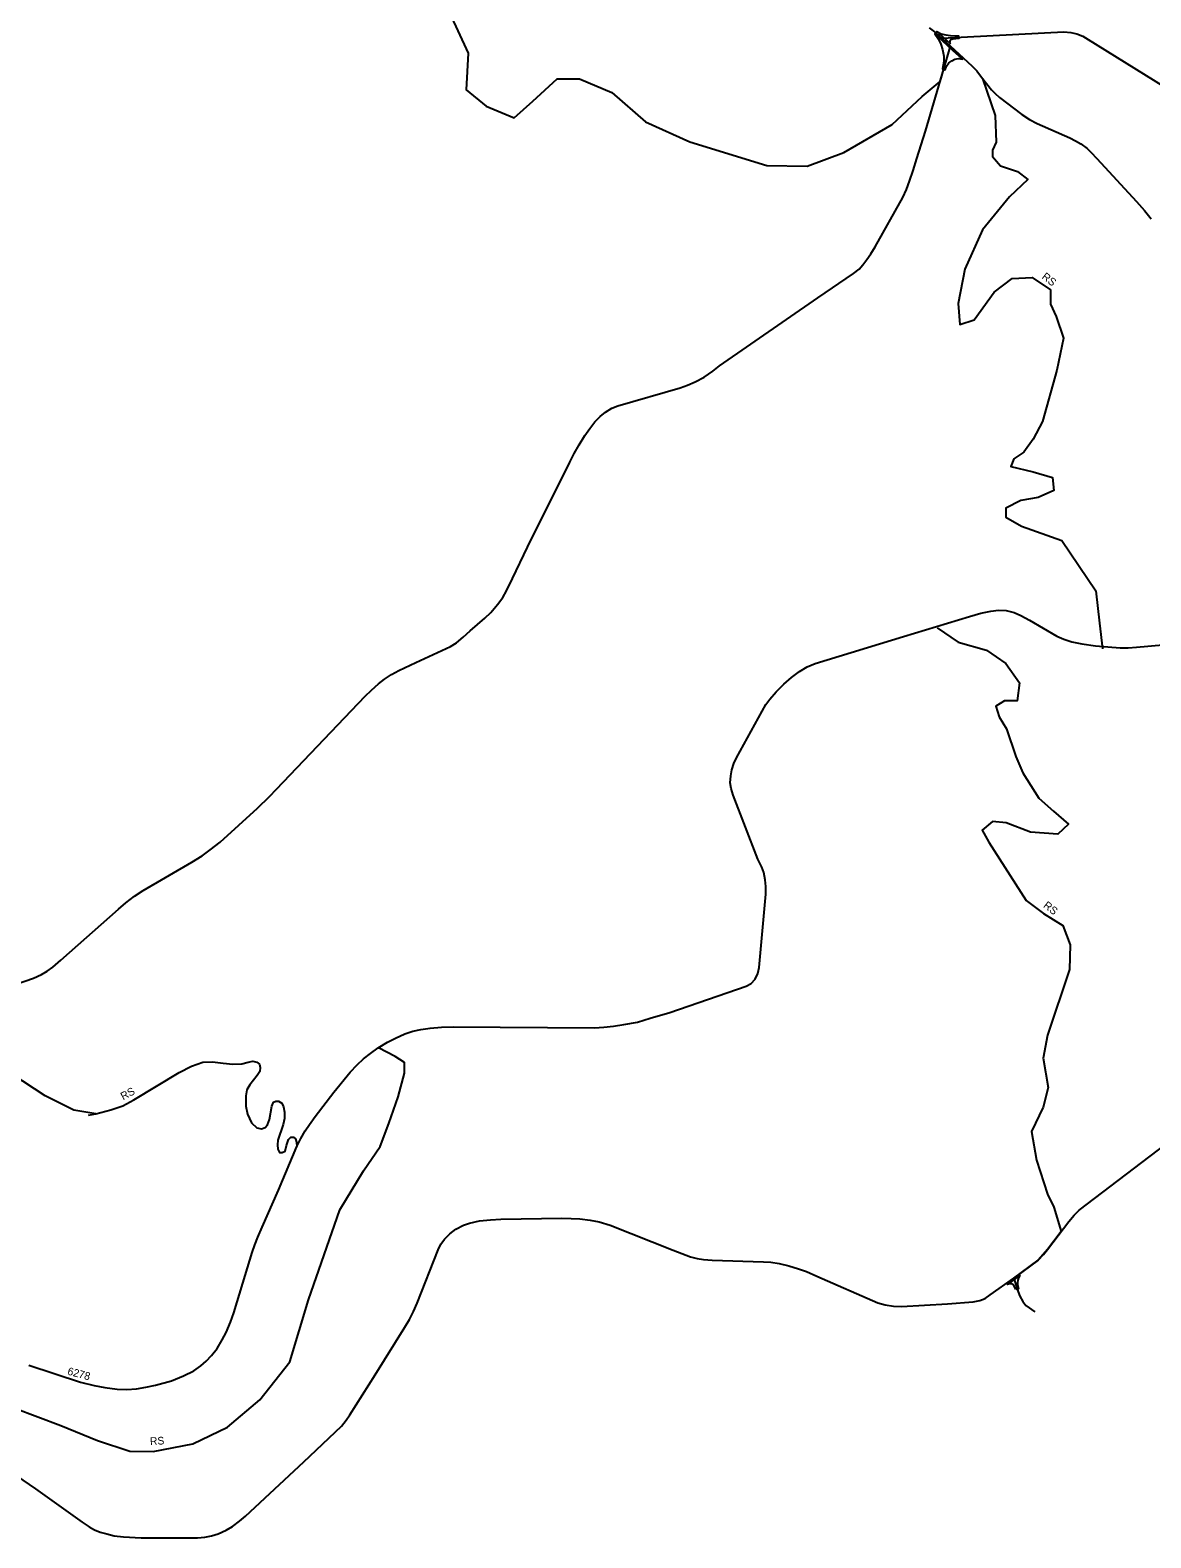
# Model space of a CAD drawing. Extents: x -546703 to -534152, y -1046534 to -1035676.
# Drawn here: x -544245 to -542791, y -1045260 to -1043304 of the extents above; entities that cross this region are included whole.
import ezdxf

# ---------------------------------------------------------------- set-up
doc = ezdxf.new("R2010")
doc.units = 0
doc.layers.add('Vrstva 11', color=7, linetype='Continuous')
doc.layers.add('Vrstva 22', color=7, linetype='Continuous')

msp = doc.modelspace()

# ---------------------------------------------------------------- linework, layer by layer
at = {"layer": 'Vrstva 11'}
for points in [[(-543078.1, -1043300.5), (-543069.5, -1043306.9), (-543062, -1043313.8), (-543050.4, -1043324.4), (-543022.8, -1043349.7), (-543016.5, -1043356.5), (-543010.3, -1043364.4), (-542997.5, -1043381.2), (-542992.8, -1043385.9), (-542987, -1043391.1), (-542958, -1043413.2), (-542948, -1043419.6), (-542937.9, -1043424.7), (-542895.5, -1043443.3), (-542888.3, -1043447.1), (-542881.4, -1043451.2), (-542873.1, -1043457.2), (-542868, -1043462.2), (-542860.8, -1043470), (-542809.2, -1043526.1), (-542798.9, -1043537.6), (-542790, -1043548.6)], [(-543062, -1043313.8), (-542903.6, -1043305.9), (-542894.5, -1043306.7), (-542886.4, -1043308.3), (-542878.9, -1043311.3), (-542872.1, -1043315.6), (-542762.3, -1043383.6)], [(-544317.4, -1044560.2), (-544240.7, -1044533.7), (-544230.6, -1044529.3), (-544223.3, -1044524.8), (-544216, -1044519.4), (-544205.6, -1044510.7), (-544130.5, -1044444.2), (-544121, -1044436), (-544109.9, -1044427.5), (-544098.6, -1044420.2), (-544035.2, -1044383.4), (-544022.1, -1044375.2), (-544011.4, -1044367.5), (-543998.7, -1044357.4), (-543950, -1044313.2), (-543934.7, -1044298), (-543925.6, -1044288.5), (-543810.3, -1044168), (-543802.1, -1044159.9), (-543793.2, -1044152), (-543785.1, -1044145.9), (-543776.2, -1044139.9), (-543766.7, -1044134.4), (-543744.7, -1044124.3), (-543699.5, -1044103.5), (-543691.9, -1044098.7), (-543683, -1044091.2), (-543674.1, -1044083.3), (-543654.9, -1044066.8), (-543647.3, -1044059.1), (-543638.4, -1044049), (-543631.9, -1044039.7), (-543627.1, -1044031), (-543619, -1044015.3), (-543599.6, -1043974.7), (-543544.7, -1043864), (-543538.9, -1043852.9), (-543532.4, -1043841.6), (-543525.1, -1043829.7), (-543518.7, -1043820.4), (-543512.2, -1043811.9), (-543505.4, -1043804.8), (-543498.5, -1043799.2), (-543490.2, -1043794.3), (-543482.4, -1043791.1), (-543401.6, -1043767.9), (-543391.9, -1043764.2), (-543382.2, -1043760), (-543370.3, -1043753.7), (-543359.2, -1043746.3), (-543350.5, -1043739.4), (-543222.6, -1043650.9), (-543176.4, -1043619.2), (-543169.3, -1043613.6), (-543164.2, -1043607.9), (-543159, -1043601.2), (-543153.8, -1043593.8), (-543148.5, -1043584.9), (-543112.6, -1043520.9), (-543107.7, -1043510.4), (-543103.7, -1043499.7), (-543099.1, -1043485.7), (-543094.2, -1043470.2), (-543083.1, -1043434.8), (-543050.4, -1043324.4)], [(-544246.9, -1045036.3), (-544179.8, -1045058.1), (-544162.3, -1045062.3), (-544148.1, -1045065.2), (-544132.1, -1045067.2), (-544119.9, -1045067.5), (-544107.3, -1045066.7), (-544095.1, -1045064.8), (-544082.6, -1045062), (-544061.6, -1045056.3), (-544046.1, -1045050.1), (-544032.9, -1045043.3), (-544023.5, -1045037.1), (-544016.7, -1045030.9), (-544009.7, -1045023.4), (-544002.7, -1045014.6), (-543995.8, -1045003.4), (-543991, -1044993.6), (-543985.3, -1044980.4), (-543981, -1044968), (-543969.2, -1044929.5), (-543957.2, -1044890.1), (-543953.7, -1044880.1), (-543949.6, -1044869.9), (-543944.3, -1044857.2), (-543922.8, -1044808.8), (-543898.9, -1044752.4), (-543893.8, -1044741.9), (-543888.1, -1044731.9), (-543882.8, -1044723.7), (-543875.4, -1044713.5), (-543850.9, -1044681.8), (-543829.9, -1044655.9), (-543820.9, -1044646.3), (-543812.4, -1044638.4), (-543803.5, -1044631.6), (-543793.5, -1044624.4), (-543781.2, -1044616.9), (-543770.9, -1044611.6), (-543758.7, -1044606.2), (-543748.7, -1044602.7), (-543738.2, -1044600.4), (-543725.8, -1044598.7), (-543711.1, -1044597.5), (-543696, -1044597), (-543512.5, -1044598.2), (-543500.8, -1044597.5), (-543488, -1044596), (-543474.8, -1044594.2), (-543457.1, -1044590.9), (-543440.3, -1044585.9), (-543414.8, -1044578.5), (-543315.9, -1044544.1), (-543309.5, -1044540.8), (-543304, -1044535.1), (-543300.7, -1044527.8), (-543298.8, -1044519.9), (-543298.2, -1044510.4), (-543290.5, -1044425), (-543290.2, -1044414.8), (-543291, -1044406.1), (-543293, -1044396.8), (-543295.7, -1044389.8), (-543300.7, -1044379.6), (-543332.9, -1044296.3), (-543335.5, -1044287.6), (-543336.4, -1044280.3), (-543335.9, -1044271.3), (-543334.5, -1044263.3), (-543331.9, -1044255.1), (-543328.4, -1044247.9), (-543290.3, -1044178.8), (-543285.3, -1044171.8), (-543277, -1044162.1), (-543267, -1044152.3), (-543257.1, -1044143.8), (-543246.5, -1044135.8), (-543236.5, -1044129.7), (-543226.1, -1044125.4), (-543111.4, -1044090.4), (-543026, -1044064.5), (-543011.1, -1044060.2), (-542998.3, -1044057.5), (-542988.1, -1044056.3), (-542978.4, -1044056.8), (-542968.1, -1044059.2), (-542959.1, -1044063.2), (-542947.9, -1044069.3), (-542912.6, -1044090.2), (-542903.4, -1044094), (-542893, -1044097.4), (-542880.2, -1044100), (-542862.2, -1044102.4), (-542830.2, -1044105), (-542819.8, -1044105), (-542809, -1044104.5), (-542726.1, -1044097)], [(-544330.5, -1045134), (-544238.5, -1045196.6), (-544177.9, -1045239.8), (-544168.8, -1045245.8), (-544161.7, -1045249.9), (-544154.3, -1045252.7), (-544145.9, -1045255.2), (-544136.3, -1045257.4), (-544124, -1045259), (-544101.1, -1045260.1), (-544027.9, -1045260.2), (-544018.4, -1045259.4), (-544009.7, -1045257.8), (-544001, -1045255.2), (-543990.9, -1045250.3), (-543982.4, -1045245.4), (-543973.6, -1045238.7), (-543965.6, -1045232.1), (-543890.2, -1045161.7), (-543841.3, -1045115.1), (-543835.1, -1045107.6), (-543830.2, -1045100.5), (-543797.5, -1045048.8), (-543758.7, -1044986.6), (-543753, -1044976.8), (-543747.6, -1044966.3), (-543742.8, -1044955.8), (-543715.8, -1044886.6), (-543712, -1044879), (-543707.3, -1044872.4), (-543700.7, -1044865.8), (-543692.6, -1044859.8), (-543682.6, -1044854.4), (-543674.8, -1044851.7), (-543661.9, -1044848.9), (-543647.8, -1044847.3), (-543634.4, -1044846.6), (-543555, -1044845.2), (-543542.9, -1044845.6), (-543531.7, -1044846.3), (-543518.3, -1044847.8), (-543506.7, -1044850.3), (-543492.4, -1044854.4), (-543410.4, -1044887), (-543388, -1044895.4), (-543379.5, -1044897.7), (-543371.3, -1044899.1), (-543360.1, -1044899.9), (-543293.5, -1044901.8), (-543283.7, -1044902.6), (-543273.1, -1044904), (-543260.5, -1044907.2), (-543247.8, -1044910.9), (-543237.3, -1044914.6), (-543224.2, -1044920.5), (-543145, -1044955.1), (-543135.4, -1044957.8), (-543124.7, -1044959.4), (-543114, -1044959.8), (-543054.7, -1044956.5), (-543021.2, -1044953.9), (-543012.4, -1044952.3), (-543005.7, -1044949.5), (-542999, -1044945), (-542968.4, -1044923.4), (-542937, -1044899.7), (-542929.8, -1044892.3), (-542924.6, -1044885.9), (-542897.1, -1044849.6), (-542890.2, -1044841.4), (-542883.5, -1044834.9), (-542771.4, -1044749.6)], [(-542968.4, -1044923.4), (-542964.2, -1044937.6), (-542960.7, -1044946.6), (-542956.9, -1044953.6), (-542952.8, -1044958.7), (-542941.3, -1044967.1)]]:
    msp.add_lwpolyline(points, dxfattribs=at)
for points in [[(-543051.7, -1043325.9), (-543063.3, -1043315.3), (-543070.8, -1043308.5), (-543066.2, -1043315.4), (-543063, -1043321.9), (-543061, -1043328.7), (-543059.3, -1043337.2), (-543059.1, -1043344.3), (-543060.9, -1043353.8), (-543057.6, -1043355), (-543055.7, -1043350.2), (-543052.6, -1043346.1), (-543049, -1043343.3), (-543045, -1043341.1), (-543040.2, -1043340.3), (-543035, -1043341.2)], [(-543060.6, -1043312.3), (-543068.2, -1043305.4), (-543062.7, -1043308.2), (-543056.7, -1043309.7), (-543050.4, -1043310.6), (-543040, -1043310.9), (-543039.6, -1043314.4), (-543047.7, -1043315.4), (-543050.2, -1043316.3), (-543051.6, -1043317.9), (-543051.7, -1043319.2), (-543051.1, -1043321)], [(-542965.9, -1044938.1), (-542968, -1044933.6), (-542969.7, -1044931.5), (-542971.5, -1044930.6), (-542973.4, -1044930.4), (-542976.8, -1044931.5), (-542967.4, -1044924.8), (-542960.5, -1044919.6), (-542962.3, -1044922.8), (-542963.1, -1044925.8), (-542963.5, -1044929.2), (-542963.5, -1044932.4), (-542962.5, -1044937)]]:
    msp.add_lwpolyline(points, close=True, dxfattribs=at)
at = {"layer": 'Vrstva 22'}
for points in [[(-543700.9, -1043281.1), (-543676.7, -1043333.5), (-543679.1, -1043381.1), (-543653.3, -1043402.1), (-543617, -1043417.4), (-543592.8, -1043395.6), (-543561.3, -1043366.6), (-543532.3, -1043366.6), (-543490.3, -1043384.3), (-543446.4, -1043422.7), (-543389.1, -1043448.5), (-543289.1, -1043479.1), (-543236.6, -1043479.9), (-543189.1, -1043462.2), (-543126.1, -1043425.9), (-543087.4, -1043389.6), (-543064, -1043370.3), (-543050.4, -1043324.4)], [(-543009, -1043366.1), (-542992.8, -1043414.3), (-542991.2, -1043449), (-542996, -1043459.4), (-542996, -1043467.5), (-542985.5, -1043479.6), (-542963.8, -1043486.9), (-542950, -1043497.3), (-542974.2, -1043519.9), (-543008.9, -1043562.7), (-543031.9, -1043613.9), (-543040.8, -1043658.3), (-543038.4, -1043685.7), (-543019.8, -1043679.3), (-542994, -1043643.8), (-542970.6, -1043626), (-542944.8, -1043624.4), (-542920.6, -1043640.6), (-542920.6, -1043659.1), (-542913.3, -1043675.2), (-542903.7, -1043703.5), (-542912.5, -1043744.6), (-542931.1, -1043811.6), (-542943.2, -1043834.2), (-542955.3, -1043851.1), (-542968.2, -1043860), (-542972.2, -1043869.7), (-542943.2, -1043876.9), (-542918.2, -1043884.2), (-542916.6, -1043901.1), (-542936.7, -1043910), (-542959.3, -1043914), (-542978.7, -1043923.7), (-542978.7, -1043935.8), (-542958.5, -1043947.1), (-542906.1, -1043965.7), (-542862.1, -1044031.4), (-542857.3, -1044073.3), (-542853.2, -1044106.4)], [(-544246.9, -1045036.3), (-544179.8, -1045058.1), (-544162.3, -1045062.3), (-544148.1, -1045065.2), (-544132.1, -1045067.2), (-544119.9, -1045067.5), (-544107.3, -1045066.7), (-544095.1, -1045064.8), (-544082.6, -1045062), (-544061.6, -1045056.3), (-544046.1, -1045050.1), (-544032.9, -1045043.3), (-544023.5, -1045037.1), (-544016.7, -1045030.9), (-544009.7, -1045023.4), (-544002.7, -1045014.6), (-543995.8, -1045003.4), (-543991, -1044993.6), (-543985.3, -1044980.4), (-543981, -1044968), (-543969.2, -1044929.5), (-543957.2, -1044890.1), (-543953.7, -1044880.1), (-543949.6, -1044869.9), (-543944.3, -1044857.2), (-543922.8, -1044808.8), (-543898.9, -1044752.4), (-543893.8, -1044741.9), (-543888.1, -1044731.9), (-543882.8, -1044723.7), (-543875.4, -1044713.5), (-543850.9, -1044681.8), (-543829.9, -1044655.9), (-543820.9, -1044646.3), (-543812.4, -1044638.4), (-543803.5, -1044631.6), (-543793.5, -1044624.4), (-543781.2, -1044616.9), (-543770.9, -1044611.6), (-543758.7, -1044606.2), (-543748.7, -1044602.7), (-543738.2, -1044600.4), (-543725.8, -1044598.7), (-543711.1, -1044597.5), (-543696, -1044597), (-543512.5, -1044598.2), (-543500.8, -1044597.5), (-543488, -1044596), (-543474.8, -1044594.2), (-543457.1, -1044590.9), (-543440.3, -1044585.9), (-543414.8, -1044578.5), (-543315.9, -1044544.1), (-543309.5, -1044540.8), (-543304, -1044535.1), (-543300.7, -1044527.8), (-543298.8, -1044519.9), (-543298.2, -1044510.4), (-543290.5, -1044425), (-543290.2, -1044414.8), (-543291, -1044406.1), (-543293, -1044396.8), (-543295.7, -1044389.8), (-543300.7, -1044379.6), (-543332.9, -1044296.3), (-543335.5, -1044287.6), (-543336.4, -1044280.3), (-543335.9, -1044271.3), (-543334.5, -1044263.3), (-543331.9, -1044255.1), (-543328.4, -1044247.9), (-543290.3, -1044178.8), (-543285.3, -1044171.8), (-543277, -1044162.1), (-543267, -1044152.3), (-543257.1, -1044143.8), (-543246.5, -1044135.8), (-543236.5, -1044129.7), (-543226.1, -1044125.4), (-543111.4, -1044090.4), (-543026, -1044064.5), (-543011.1, -1044060.2), (-542998.3, -1044057.5), (-542988.1, -1044056.3), (-542978.4, -1044056.8), (-542968.1, -1044059.2), (-542959.1, -1044063.2), (-542947.9, -1044069.3), (-542912.6, -1044090.2), (-542903.4, -1044094), (-542893, -1044097.4), (-542880.2, -1044100), (-542862.2, -1044102.4), (-542830.2, -1044105), (-542819.8, -1044105), (-542809, -1044104.5), (-542726.1, -1044097)], [(-543067.8, -1044079), (-543040.8, -1044098), (-543003.7, -1044108.4), (-542978.7, -1044125.4), (-542960.9, -1044150.4), (-542964.2, -1044173.8), (-542980.3, -1044173.8), (-542991.6, -1044181), (-542987.5, -1044194.8), (-542977.9, -1044210.1), (-542965.8, -1044246.4), (-542956.9, -1044267.4), (-542935.9, -1044300.4), (-542917, -1044317), (-542897.6, -1044333.9), (-542911.3, -1044346.8), (-542946.8, -1044344.4), (-542978.3, -1044332.3), (-542996, -1044330.7), (-543009.7, -1044342), (-543000.8, -1044357.3), (-542952.4, -1044433.1), (-542929.9, -1044450.1), (-542904.9, -1044465.4), (-542895.2, -1044490.4), (-542896, -1044522.7), (-542924.6, -1044607.8), (-542930.3, -1044637.6), (-542923.8, -1044675.6), (-542930.3, -1044701.4), (-542945.6, -1044732.8), (-542939.1, -1044769.9), (-542924.6, -1044814.3), (-542916.3, -1044831.1), (-542907, -1044862.7), (-542924.6, -1044885.9), (-542937, -1044899.7), (-542968.4, -1044923.4), (-542964.2, -1044937.6), (-542960.7, -1044946.6), (-542956.9, -1044953.6), (-542952.8, -1044958.7), (-542941.3, -1044967.1)], [(-544159.9, -1044710), (-544188.6, -1044705.2), (-544225.7, -1044686.6), (-544268.4, -1044658.4), (-544302.3, -1044631.7), (-544324.9, -1044620.5), (-544354.8, -1044609.2), (-544382.2, -1044589.8), (-544405.9, -1044576.3)], [(-544534.9, -1045164.1), (-544480.6, -1045127.5), (-544411.2, -1045090.4), (-544360.4, -1045073.4), (-544312.8, -1045074.2), (-544265.2, -1045092), (-544205.5, -1045114.6), (-544157.9, -1045133.9), (-544116, -1045147.6), (-544085.7, -1045148), (-544034.1, -1045138.4), (-543988.9, -1045116.6), (-543947, -1045081.1), (-543908.2, -1045031.9), (-543884.1, -1044951.2), (-543843.3, -1044834.6), (-543812.7, -1044783.8), (-543790.9, -1044752.3), (-543779.6, -1044722.5), (-543767.5, -1044687.8), (-543759.4, -1044657.2), (-543759.4, -1044643.4), (-543771.5, -1044635.4), (-543793.2, -1044624.2)], [(-544169.3, -1044711.6), (-544159.9, -1044710), (-544140.4, -1044704.8), (-544125, -1044699.4), (-544110.6, -1044691.7), (-544052, -1044656.4), (-544035.6, -1044648.1), (-544021.2, -1044643), (-544008.7, -1044642.3), (-543994.6, -1044644), (-543982.1, -1044645.6), (-543970.3, -1044645.2), (-543962.3, -1044642.7), (-543956.2, -1044641.7), (-543950.8, -1044642.7), (-543947.5, -1044645.6), (-543946.6, -1044649.7), (-543947.2, -1044655.2), (-543950.4, -1044660), (-543960, -1044672.2), (-543963.9, -1044678.9), (-543965.2, -1044686.6), (-543965.2, -1044700), (-543963.2, -1044710.3), (-543957.8, -1044721.5), (-543951.1, -1044728.2), (-543945, -1044729.5), (-543940.2, -1044727.6), (-543937.3, -1044724.1), (-543934.4, -1044717.3), (-543931.5, -1044700), (-543929.3, -1044694.9), (-543926.4, -1044693.3), (-543922.9, -1044693.3), (-543918.7, -1044695.9), (-543916.2, -1044700.7), (-543914.9, -1044707.7), (-543915.2, -1044716.1), (-543916.8, -1044723.7), (-543923.8, -1044744.3), (-543924.2, -1044750), (-543923.8, -1044755.8), (-543921.6, -1044760), (-543918.1, -1044760.3), (-543914.2, -1044758.4), (-543912.6, -1044751), (-543910.1, -1044743.3), (-543906.9, -1044740.4), (-543903.4, -1044740.1), (-543900.8, -1044742.3), (-543899.5, -1044746.5), (-543898.9, -1044752.4)]]:
    msp.add_lwpolyline(points, dxfattribs=at)

# ---------------------------------------------------------------- texts
for s, rotation, p in [('RS', 322.0469, (-542932.9, -1043625.1)), ('RS', 322.0469, (-542930.9, -1044441.1)), ('RS', 28.0869, (-544124.6, -1044692.4)), ('6278', 344.9848, (-544197.5, -1045048.2)), ('RS', 2.7828, (-544089.5, -1045139.8))]:
    msp.add_text(s, height=10, rotation=rotation, dxfattribs=at).set_placement(p)

doc.saveas('drawing.dxf')
